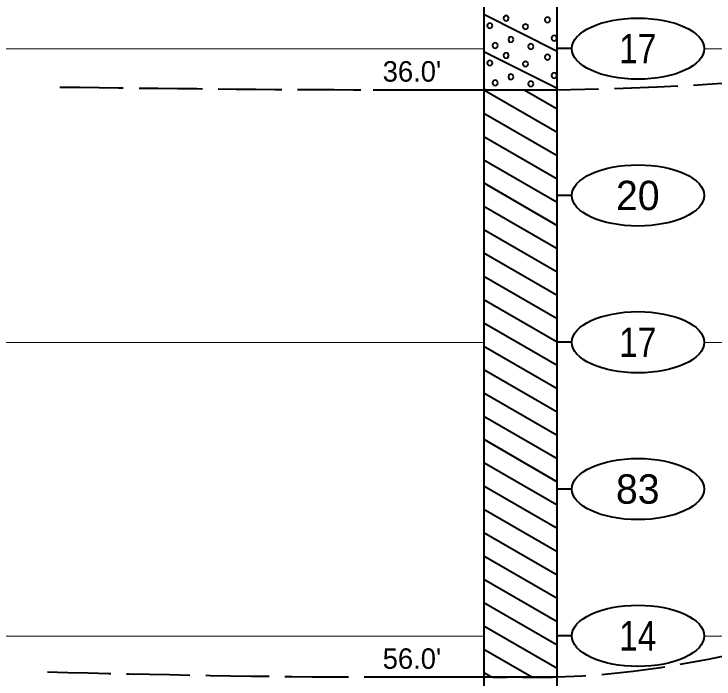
# Model space of a CAD drawing. Extents: x -76 to 974, y -1080 to -735.
# Drawn here: x 879.5 to 903.36, y -983.55 to -960.9 of the extents above; entities that cross this region are included whole.
import ezdxf
from ezdxf.enums import TextEntityAlignment as Align

# ---------------------------------------------------------------- set-up
doc = ezdxf.new("R2010")
doc.units = 0
doc.header["$LTSCALE"] = 0.36
doc.linetypes.add('LONG_DASHED', pattern=[7.5, 6, -1.5])
for name, color, linetype, lineweight in [('27', 7, 'Continuous', 40), ('28', 7, 'LONG_DASHED', 60), ('7', 7, 'Continuous', 13)]:
    doc.layers.add(name, color=color, linetype=linetype, lineweight=lineweight)

msp = doc.modelspace()

# ---------------------------------------------------------------- linework, layer by layer
at = {"layer": '27'}
for p, q in [((895.5077, -949.4789), (895.5077, -963.4789)), ((898.0077, -963.4789), (898.0077, -949.4789)), ((895.5077, -960.9089), (898.0077, -962.1589)), ((898.5077, -962.0789), (898.0077, -962.0789)), ((895.5077, -962.1789), (898.0077, -963.4289)), ((891.7402, -963.4789), (895.5076, -963.4789)), ((895.5077, -963.4489), (895.5677, -963.4789)), ((895.5077, -963.4789), (898.0077, -963.4789)), ((895.5077, -963.4789), (898.0077, -964.9223)), ((895.5077, -963.4789), (895.5077, -983.4789)), ((896.8824, -963.4789), (898.0077, -964.1286)), ((896.8824, -963.4789), (898.0077, -964.1286)), ((898.0077, -983.4789), (898.0077, -963.4789)), ((895.5077, -964.2727), (898.0077, -965.7161)), ((895.5077, -964.2727), (898.0077, -965.7161)), ((895.5077, -965.0664), (898.0077, -966.5098)), ((895.5077, -965.8602), (898.0077, -967.3036)), ((895.5077, -965.8602), (898.0077, -967.3036)), ((895.5077, -966.6539), (898.0077, -968.0973)), ((898.5077, -967.0789), (898.0077, -967.0789)), ((895.5077, -967.4477), (898.0077, -968.8911)), ((895.5077, -967.4477), (898.0077, -968.8911)), ((895.5077, -968.2414), (898.0077, -969.6848)), ((895.5077, -969.0352), (898.0077, -970.4786)), ((895.5077, -969.0352), (898.0077, -970.4786)), ((895.5077, -969.8289), (898.0077, -971.2723)), ((895.5077, -970.6227), (898.0077, -972.0661)), ((895.5077, -970.6227), (898.0077, -972.0661)), ((895.5077, -971.4164), (898.0077, -972.8598)), ((898.5077, -972.0789), (898.0077, -972.0789)), ((895.5077, -972.2102), (898.0077, -973.6536)), ((895.5077, -972.2102), (898.0077, -973.6536)), ((895.5077, -973.0039), (898.0077, -974.4473)), ((895.5077, -973.7977), (898.0077, -975.2411)), ((895.5077, -973.7977), (898.0077, -975.2411)), ((895.5077, -974.5914), (898.0077, -976.0348)), ((895.5077, -975.3852), (898.0077, -976.8286)), ((895.5077, -975.3852), (898.0077, -976.8286)), ((895.5077, -976.1789), (898.0077, -977.6223)), ((895.5077, -976.9727), (898.0077, -978.4161)), ((895.5077, -976.9727), (898.0077, -978.4161)), ((898.5077, -977.0789), (898.0077, -977.0789)), ((895.5077, -977.7664), (898.0077, -979.2098)), ((895.5077, -978.5602), (898.0077, -980.0036)), ((895.5077, -978.5602), (898.0077, -980.0036)), ((895.5077, -979.3539), (898.0077, -980.7973)), ((895.5077, -980.1477), (898.0077, -981.5911)), ((895.5077, -980.1477), (898.0077, -981.5911)), ((895.5077, -980.9414), (898.0077, -982.3848)), ((895.5077, -981.7352), (898.0077, -983.1786)), ((895.5077, -981.7352), (898.0077, -983.1786)), ((898.5077, -982.0789), (898.0077, -982.0789)), ((895.5077, -982.5289), (897.1531, -983.4789)), ((895.5077, -983.3227), (895.7783, -983.4789)), ((895.5077, -983.3227), (895.7783, -983.4789)), ((891.7402, -983.4789), (895.5076, -983.4789)), ((895.5077, -983.4789), (898.0077, -983.4789)), ((895.5077, -983.4789), (895.5077, -994.4789)), ((898.0077, -994.4789), (898.0077, -983.4789))]:
    msp.add_line(p, q, dxfattribs=at)
for points in [[(896.3583, -961.044), (896.3463, -960.9996), (896.3138, -960.9671), (896.2694, -960.9551), (896.2249, -960.9671), (896.1924, -960.9996), (896.1805, -961.044), (896.1924, -961.0885), (896.2249, -961.121), (896.2694, -961.1329), (896.3138, -961.121), (896.3463, -961.0885)], [(897.7732, -961.0949), (897.7613, -961.0504), (897.7287, -961.0179), (897.6843, -961.006), (897.6398, -961.0179), (897.6073, -961.0504), (897.5954, -961.0949), (897.6073, -961.1393), (897.6398, -961.1719), (897.6843, -961.1838), (897.7287, -961.1719), (897.7613, -961.1393)], [(895.8053, -961.2958), (895.7933, -961.2513), (895.7608, -961.2188), (895.7164, -961.2069), (895.6719, -961.2188), (895.6394, -961.2513), (895.6275, -961.2958), (895.6394, -961.3402), (895.6719, -961.3727), (895.7164, -961.3847), (895.7608, -961.3727), (895.7933, -961.3402)], [(897.0206, -961.3288), (897.0087, -961.2844), (896.9761, -961.2518), (896.9317, -961.2399), (896.8872, -961.2518), (896.8547, -961.2844), (896.8428, -961.3288), (896.8547, -961.3733), (896.8872, -961.4058), (896.9317, -961.4177), (896.9761, -961.4058), (897.0087, -961.3733)], [(896.5248, -961.7661), (896.5129, -961.7217), (896.4803, -961.6891), (896.4359, -961.6772), (896.3914, -961.6891), (896.3589, -961.7217), (896.347, -961.7661), (896.3589, -961.8106), (896.3914, -961.8431), (896.4359, -961.855), (896.4803, -961.8431), (896.5129, -961.8106)], [(897.9995, -961.7229), (897.9876, -961.6785), (897.955, -961.6459), (897.9106, -961.634), (897.8661, -961.6459), (897.8336, -961.6785), (897.8217, -961.7229), (897.8336, -961.7674), (897.8661, -961.7999), (897.9106, -961.8118), (897.955, -961.7999), (897.9876, -961.7674)], [(895.9896, -961.9746), (895.9777, -961.9302), (895.9451, -961.8976), (895.9007, -961.8857), (895.8562, -961.8976), (895.8237, -961.9302), (895.8118, -961.9746), (895.8237, -962.0191), (895.8562, -962.0516), (895.9007, -962.0635), (895.9451, -962.0516), (895.9777, -962.0191)], [(897.2024, -962.0077), (897.1905, -961.9632), (897.1579, -961.9307), (897.1135, -961.9188), (897.069, -961.9307), (897.0365, -961.9632), (897.0246, -962.0077), (897.0365, -962.0521), (897.069, -962.0847), (897.1135, -962.0966), (897.1579, -962.0847), (897.1905, -962.0521)], [(896.3583, -962.3152), (896.3464, -962.2708), (896.3139, -962.2383), (896.2694, -962.2263), (896.225, -962.2383), (896.1925, -962.2708), (896.1805, -962.3152), (896.1925, -962.3597), (896.225, -962.3922), (896.2694, -962.4041), (896.3139, -962.3922), (896.3464, -962.3597)], [(897.7732, -962.3662), (897.7613, -962.3217), (897.7287, -962.2892), (897.6843, -962.2773), (897.6398, -962.2892), (897.6073, -962.3217), (897.5954, -962.3662), (897.6073, -962.4106), (897.6398, -962.4432), (897.6843, -962.4551), (897.7287, -962.4432), (897.7613, -962.4106)], [(895.8053, -962.567), (895.7933, -962.5226), (895.7608, -962.49), (895.7164, -962.4781), (895.6719, -962.49), (895.6394, -962.5226), (895.6275, -962.567), (895.6394, -962.6115), (895.6719, -962.644), (895.7164, -962.6559), (895.7608, -962.644), (895.7933, -962.6115)], [(897.0206, -962.6001), (897.0087, -962.5556), (896.9761, -962.5231), (896.9317, -962.5112), (896.8872, -962.5231), (896.8547, -962.5556), (896.8428, -962.6001), (896.8547, -962.6445), (896.8872, -962.6771), (896.9317, -962.689), (896.9761, -962.6771), (897.0087, -962.6445)], [(896.5248, -963.0374), (896.5129, -962.993), (896.4803, -962.9604), (896.4359, -962.9485), (896.3914, -962.9604), (896.3589, -962.993), (896.347, -963.0374), (896.3589, -963.0819), (896.3914, -963.1144), (896.4359, -963.1263), (896.4803, -963.1144), (896.5129, -963.0819)], [(897.9995, -962.9942), (897.9876, -962.9497), (897.955, -962.9172), (897.9106, -962.9053), (897.8661, -962.9172), (897.8336, -962.9497), (897.8217, -962.9942), (897.8336, -963.0386), (897.8661, -963.0712), (897.9106, -963.0831), (897.955, -963.0712), (897.9876, -963.0386)], [(895.9896, -963.2459), (895.9777, -963.2014), (895.9451, -963.1689), (895.9007, -963.157), (895.8562, -963.1689), (895.8237, -963.2014), (895.8118, -963.2459), (895.8237, -963.2903), (895.8562, -963.3229), (895.9007, -963.3348), (895.9451, -963.3229), (895.9777, -963.2903)], [(897.2024, -963.2789), (897.1905, -963.2345), (897.1579, -963.202), (897.1135, -963.19), (897.069, -963.202), (897.0365, -963.2345), (897.0246, -963.2789), (897.0365, -963.3234), (897.069, -963.3559), (897.1135, -963.3678), (897.1579, -963.3559), (897.1905, -963.3234)]]:
    msp.add_lwpolyline(points, close=True, dxfattribs=at)
for centre in [(900.7651, -962.0789), (900.7651, -967.0789), (900.7651, -972.0789), (900.7651, -977.0789), (900.7651, -982.0789)]:
    msp.add_ellipse(centre, major_axis=(2.2574, 0), ratio=0.461538, dxfattribs=at)
at = {"layer": '28', "lineweight": 40}
for points in [[(881.0623, -963.3858), (891.7402, -963.4789), (895.5076, -963.4789), (898.0077, -963.4789), (925.2403, -961.6789), (929.0077, -961.6789), (931.5077, -961.6789), (945.5373, -961.3929)], [(880.636, -983.31), (891.7402, -983.4789), (895.5076, -983.4789), (898.0077, -983.4789), (925.2403, -977.6789), (929.0077, -977.6789), (931.5077, -977.6789), (945.1367, -977.6971)]]:
    msp.add_spline(points, degree=3, dxfattribs=at)
at = {"layer": '7'}
for p, q in [((864.9092, -962.09), (895.5077, -962.09)), ((898.0077, -962.09), (898.5079, -962.09)), ((903.0224, -962.09), (929.0077, -962.09)), ((864.9092, -972.09), (895.5077, -972.09)), ((898.0077, -972.09), (898.5079, -972.09)), ((903.0224, -972.09), (929.0077, -972.09)), ((864.9092, -982.09), (895.5077, -982.09)), ((898.0077, -982.09), (898.5079, -982.09)), ((903.0224, -982.09), (929.0077, -982.09))]:
    msp.add_line(p, q, dxfattribs=at)

# ---------------------------------------------------------------- texts
at = {"layer": '27', "width": 0.85}
for s, p in [('17', (900.7579, -962.5788)), ('17', (900.7579, -972.5788)), ('14', (900.7579, -982.5788))]:
    msp.add_text(s, height=1, dxfattribs=at).set_placement(p, align=Align.CENTER)
at = {"layer": '27'}
for s, p in [("36.0'", (892.0643, -963.2025)), ("56.0'", (892.0643, -983.2025))]:
    msp.add_text(s, height=0.6976, dxfattribs=at).set_placement(p)
for s, p in [('20', (900.758, -967.5788)), ('83', (900.758, -977.5788))]:
    msp.add_text(s, height=1, dxfattribs=at).set_placement(p, align=Align.CENTER)

doc.saveas('drawing.dxf')
